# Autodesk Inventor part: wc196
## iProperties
Shininess: 64.0
Length Units: 11272
Angle Units: 11279
Time Units: 11290
Mass Units: 11286
Length Display Precision: 3
Angle Display Precision: 2
Compacted: True
Part Number: wc196
Document SubType Name: Modeling
Created: 2004-08
Designer: John Blackburn
Manufacturer: Standard
Standards Organization: Custom
Material: Phenolic
Density: 0.0
Volumn: 0.0
Area: 0.0
PropertySet Name: Model Information
Control State: 0
Master: False
Checked Out: False
Author: John Blackburn
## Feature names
1. Base1
